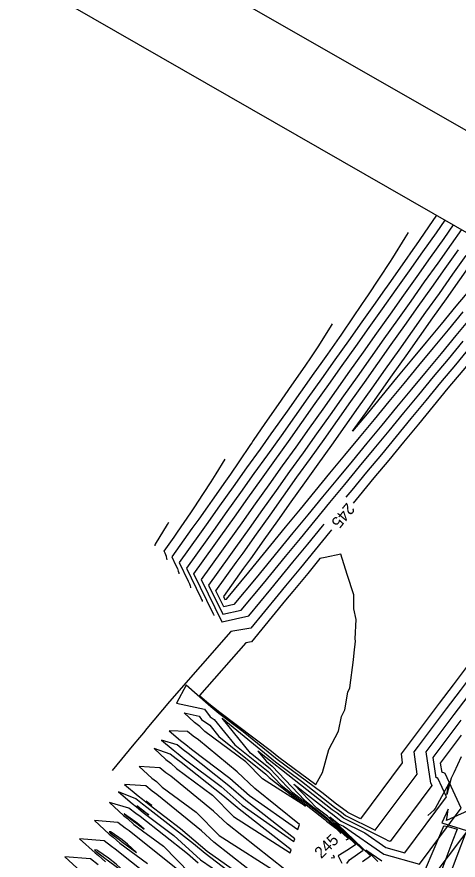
# Model space of a CAD drawing. Extents: x 1160447 to 1162032, y 616022 to 618272.
# Drawn here: x 1160902.9 to 1160997.8, y 616733 to 616914.4 of the extents above; entities that cross this region are included whole.
import ezdxf

# ---------------------------------------------------------------- set-up
doc = ezdxf.new("R2010")
doc.units = 0
for name, color, linetype in [('BORDER', 7, 'Continuous'), ('D_Contours_Major', 7, 'Continuous'), ('D_Contours_Minor', 7, 'Continuous'), ('Plot Boundary_1', 7, 'Continuous')]:
    doc.layers.add(name, color=color, linetype=linetype)

msp = doc.modelspace()

# ---------------------------------------------------------------- linework, layer by layer
at = {"layer": 'BORDER'}
msp.add_line((1161303.72, 616715.44), (1160848.31, 616976.65), dxfattribs=at)
at = {"layer": 'D_Contours_Major'}
for points in [[(1160945.35, 616785.57), (1160945.35, 616785.6), (1160945.33, 616785.67), (1160945.29, 616785.76), (1160945.23, 616785.9), (1160940.99, 616794.53), (1160945.35, 616800.64), (1160946.8, 616802.68), (1160949.71, 616806.75), (1160952.62, 616810.82), (1160955.52, 616814.9), (1160958.42, 616818.97), (1160961.32, 616823.05), (1160964.22, 616827.12), (1160967.12, 616831.2), (1160970.02, 616835.28), (1160972.92, 616839.36), (1160975.81, 616843.44), (1160978.71, 616847.52), (1160981.6, 616851.6), (1160984.49, 616855.69), (1160987.38, 616859.77), (1160990.27, 616863.85), (1160993.16, 616867.94), (1160995.07, 616870.64)], [(1161007.04, 616863.78), (1161006.95, 616863.68), (1161003.75, 616859.82), (1161000.56, 616855.97), (1160997.37, 616852.12), (1160994.18, 616848.27), (1160990.99, 616844.41), (1160987.8, 616840.56), (1160984.61, 616836.7), (1160981.42, 616832.84), (1160978.24, 616828.98), (1160975.15, 616825.24), (1160977.96, 616829.2), (1160980.85, 616833.28), (1160983.75, 616837.36), (1160986.65, 616841.44), (1160989.54, 616845.52), (1160992.43, 616849.6), (1160995.32, 616853.69), (1160998.21, 616857.77), (1161001.1, 616861.86), (1161003.78, 616865.65)], [(1160975.33, 616809.76), (1160976.62, 616811.32), (1160979.81, 616815.18), (1160982.99, 616819.04), (1160986.17, 616822.9), (1160989.36, 616826.76), (1160992.55, 616830.62), (1160995.73, 616834.47), (1160998.92, 616838.33), (1161001.83, 616841.84), (1161002.43, 616841.94), (1161006.15, 616842.54), (1161010.36, 616842.17), (1161015.21, 616841.72), (1161018.4, 616842.3), (1161024.16, 616843.33), (1161025.22, 616843.37), (1161027.33, 616843.88), (1161031.24, 616845.06), (1161035.35, 616846.28), (1161036.36, 616846.96)], [(1160932.68, 616800.56), (1160932.68, 616800.9), (1160932.68, 616800.9), (1160932.72, 616800.96), (1160935.32, 616805.18), (1160935.63, 616805.67)], [(1160970.58, 616803.99), (1160970.26, 616803.6), (1160967.08, 616799.74), (1160963.9, 616795.87), (1160960.73, 616792.01), (1160959.14, 616790.07), (1160953.22, 616782.87), (1160948.96, 616782.12), (1160935.72, 616767.07), (1160930.86, 616761.25), (1160930.13, 616760.38), (1160929.3, 616759.38), (1160928.07, 616757.9), (1160926.08, 616755.51), (1160925.42, 616754.72), (1160923.39, 616752.28)], [(1160999.76, 616774.69), (1160996.76, 616770.7), (1160993.75, 616766.7), (1160992.24, 616764.71), (1160987.73, 616758.72), (1160985.58, 616755.87), (1160985.82, 616753.88), (1160976.84, 616741.87), (1160974.12, 616743.21), (1160973.75, 616743.5), (1160971.71, 616745), (1160968.51, 616747.53), (1160958.93, 616754.62), (1160951.61, 616760.58), (1160946.36, 616764.52), (1160944.67, 616765.98), (1160944.06, 616766.45), (1160939.32, 616770.58), (1160937.26, 616766.74), (1160943.28, 616765.43), (1160944.53, 616763.8), (1160945.35, 616763.21), (1160949.8, 616757.77), (1160956.95, 616752.04), (1160959.76, 616749.08), (1160969.2, 616741.72), (1160969.56, 616741.37), (1160971.54, 616739.84), (1160972.64, 616738.78), (1160972.43, 616738.69)], [(1160998.49, 616755.2), (1160996.89, 616751.74), (1160996.37, 616750.6), (1160995.42, 616747.11), (1160995.84, 616749.45), (1160994.27, 616746.55), (1160992.93, 616744.07), (1160992.58, 616743.74), (1160991.35, 616742.56)], [(1161001.54, 616744.28), (1160995.35, 616741.48), (1160995.48, 616742.28), (1160995.71, 616743.93), (1160994.34, 616741.02), (1160994.97, 616740.81), (1160995.08, 616740.79), (1160999.65, 616739.35)], [(1160992.71, 616729.7), (1161001.7, 616741.71), (1161000.68, 616743.9)], [(1160999.34, 616738.53), (1160997.56, 616733.84), (1160995.76, 616729.09)], [(1160980.58, 616732.7), (1160977.99, 616735.17), (1160981.43, 616732.8)]]:
    msp.add_lwpolyline(points, dxfattribs=at)
at = {"layer": 'D_Contours_Minor'}
for points in [[(1160993.16, 616871.74), (1160991.46, 616869.24), (1160988.64, 616865.11), (1160988.6, 616865.05), (1160985.77, 616861.01), (1160982.9, 616856.91), (1160981.67, 616855.16), (1160980.01, 616852.82), (1160977.12, 616848.74), (1160974.23, 616844.66), (1160971.33, 616840.58), (1160968.43, 616836.5), (1160965.54, 616832.42), (1160962.64, 616828.34), (1160959.74, 616824.26), (1160956.83, 616820.19), (1160953.93, 616816.11), (1160951.03, 616812.04), (1160948.12, 616807.97), (1160945.22, 616803.89), (1160943.76, 616801.86), (1160939.4, 616795.75), (1160942.51, 616789.42), (1160942.67, 616789.07), (1160942.77, 616788.82), (1160942.81, 616788.66), (1160942.81, 616788.57)], [(1160996.81, 616869.64), (1160994.75, 616866.72), (1160991.86, 616862.64), (1160988.97, 616858.55), (1160986.08, 616854.47), (1160983.19, 616850.39), (1160980.3, 616846.3), (1160977.4, 616842.22), (1160974.5, 616838.14), (1160971.61, 616834.06), (1160968.71, 616829.99), (1160965.81, 616825.91), (1160962.91, 616821.83), (1160960.01, 616817.76), (1160957.11, 616813.68), (1160954.2, 616809.61), (1160951.3, 616805.53), (1160948.39, 616801.46), (1160946.94, 616799.42), (1160942.58, 616793.32), (1160947.03, 616784.25), (1160947.07, 616784.24), (1160952.79, 616785.49), (1160957.55, 616791.29), (1160959.14, 616793.22), (1160962.32, 616797.09), (1160965.5, 616800.95), (1160968.67, 616804.82), (1160969.04, 616805.26)], [(1160987.12, 616867.96), (1160986.4, 616866.82), (1160983.73, 616862.57), (1160983.1, 616861.56), (1160980.99, 616858.37), (1160978.23, 616854.18), (1160978.14, 616854.04), (1160975.41, 616850.05), (1160972.58, 616845.92), (1160972.25, 616845.43), (1160969.71, 616841.82), (1160968.28, 616839.78), (1160966.83, 616837.73), (1160963.94, 616833.64), (1160961.04, 616829.56), (1160958.15, 616825.48), (1160957.57, 616824.67), (1160955.25, 616821.4), (1160952.34, 616817.33), (1160949.44, 616813.26), (1160946.54, 616809.18), (1160943.63, 616805.11), (1160942.18, 616803.07), (1160937.82, 616796.97), (1160939.79, 616792.95), (1160940.06, 616792.37), (1160940.21, 616791.98), (1160940.28, 616791.72), (1160940.28, 616791.56)], [(1160998.56, 616868.64), (1160996.34, 616865.51), (1160993.45, 616861.42), (1160990.56, 616857.34), (1160987.67, 616853.25), (1160984.78, 616849.17), (1160981.88, 616845.09), (1160978.99, 616841.01), (1160976.09, 616836.93), (1160973.2, 616832.85), (1160970.3, 616828.77), (1160967.4, 616824.69), (1160964.5, 616820.61), (1160961.6, 616816.54), (1160958.69, 616812.46), (1160955.79, 616808.39), (1160952.89, 616804.32), (1160949.98, 616800.24), (1160948.53, 616798.21), (1160944.17, 616792.1), (1160947.23, 616785.85), (1160947.26, 616785.85), (1160951.2, 616786.71), (1160955.97, 616792.51), (1160957.55, 616794.44), (1160960.73, 616798.31), (1160963.91, 616802.17), (1160967.09, 616806.03), (1160970.27, 616809.89), (1160973.45, 616813.76), (1160976.63, 616817.62), (1160979.81, 616821.48), (1160983, 616825.34), (1160986.18, 616829.19), (1160989.37, 616833.05), (1160992.56, 616836.91), (1160995.75, 616840.76), (1160998.94, 616844.62)], [(1161000.54, 616849.69), (1160997.35, 616845.83), (1160994.16, 616841.98), (1160990.97, 616838.12), (1160987.78, 616834.27), (1160984.6, 616830.41), (1160981.41, 616826.55), (1160978.23, 616822.69), (1160975.04, 616818.83), (1160971.86, 616814.97), (1160968.68, 616811.11), (1160965.5, 616807.25), (1160962.32, 616803.39), (1160959.14, 616799.52), (1160955.97, 616795.66), (1160954.38, 616793.72), (1160949.61, 616787.93), (1160947.45, 616787.45), (1160947.44, 616787.46), (1160945.75, 616790.88), (1160950.11, 616796.99), (1160951.57, 616799.03), (1160954.47, 616803.1), (1160957.38, 616807.17), (1160960.28, 616811.25), (1160963.18, 616815.32), (1160966.09, 616819.4), (1160968.99, 616823.47), (1160971.88, 616827.55), (1160974.78, 616831.63), (1160977.68, 616835.71), (1160980.58, 616839.79), (1160983.47, 616843.87), (1160986.36, 616847.95), (1160989.26, 616852.04), (1160992.15, 616856.12), (1160995.04, 616860.21), (1160997.93, 616864.29)], [(1160999.51, 616863.07), (1160996.62, 616858.99), (1160993.73, 616854.9), (1160990.84, 616850.82), (1160987.95, 616846.74), (1160985.06, 616842.66), (1160982.16, 616838.57), (1160979.27, 616834.49), (1160976.37, 616830.41), (1160973.47, 616826.34), (1160970.57, 616822.26), (1160967.67, 616818.18), (1160964.77, 616814.11), (1160961.87, 616810.03), (1160958.97, 616805.96), (1160956.06, 616801.88), (1160953.15, 616797.81), (1160951.7, 616795.78), (1160947.34, 616789.67), (1160947.64, 616789.06), (1160947.64, 616789.06), (1160948.03, 616789.14), (1160952.79, 616794.94), (1160954.38, 616796.87), (1160957.56, 616800.74), (1160960.73, 616804.6), (1160963.91, 616808.47), (1160967.09, 616812.33), (1160970.27, 616816.19), (1160973.46, 616820.05), (1160976.64, 616823.91), (1160979.82, 616827.77), (1160983.01, 616831.63), (1160986.2, 616835.48), (1160989.38, 616839.34), (1160992.57, 616843.2), (1160995.76, 616847.05), (1160998.96, 616850.9)], [(1160973.79, 616811.03), (1160975.04, 616812.54), (1160978.22, 616816.4), (1160981.4, 616820.26), (1160984.59, 616824.12), (1160987.77, 616827.98), (1160990.96, 616831.83), (1160994.15, 616835.69), (1160997.34, 616839.55), (1161000.53, 616843.4), (1161003.72, 616847.25), (1161006.91, 616851.11), (1161010.1, 616854.96), (1161013.3, 616858.81), (1161014.07, 616859.74)], [(1160970.75, 616848.31), (1160970.33, 616847.64), (1160967.66, 616843.39), (1160966.24, 616841.23), (1160964.88, 616839.22), (1160962.01, 616835.12), (1160959.15, 616831.01), (1160956.28, 616826.91), (1160953.78, 616823.21), (1160953.48, 616822.76), (1160953.21, 616822.36), (1160950.66, 616818.62), (1160948.87, 616815.99), (1160947.82, 616814.5), (1160944.94, 616810.41), (1160943.91, 616808.94), (1160942.04, 616806.33), (1160940.59, 616804.29), (1160936.23, 616798.18), (1160937.07, 616796.47), (1160937.44, 616795.68), (1160937.65, 616795.14), (1160937.75, 616794.78), (1160937.75, 616794.56)], [(1160935.22, 616797.56), (1160935.21, 616797.84), (1160935.09, 616798.29), (1160934.82, 616798.98), (1160934.62, 616799.42), (1160936.77, 616802.48), (1160937.48, 616803.52), (1160938.9, 616805.59), (1160940.31, 616807.65), (1160941.04, 616808.73), (1160943.08, 616811.83), (1160944.72, 616814.33), (1160945.79, 616816.06), (1160947.76, 616819.24)], [(1160973.75, 616737.36), (1160974.23, 616737.57), (1160971.67, 616740.01), (1160970.16, 616741.18), (1160969.37, 616741.94), (1160962.32, 616747.44), (1160957.4, 616752.62), (1160953.21, 616755.98), (1160947.06, 616763.5), (1160958.56, 616754.13), (1160964.18, 616749.97), (1160971.25, 616744.39), (1160972.77, 616743.28), (1160973.64, 616742.59), (1160980.01, 616739.43), (1160989, 616751.45), (1160988.4, 616756.28), (1160989.32, 616757.5), (1160993.83, 616763.49), (1160995.34, 616765.49), (1160998.34, 616769.48), (1161001.35, 616773.48), (1161003.2, 616775.94)], [(1160999.93, 616768.26), (1160996.92, 616764.27), (1160995.42, 616762.27), (1160990.91, 616756.28), (1160991.9, 616749.52), (1160991.91, 616749.52), (1160991.92, 616749.52), (1160991.93, 616749.51), (1160991.94, 616749.51), (1160992.17, 616749.01), (1160983.19, 616737), (1160982.77, 616737.11), (1160982.29, 616737.44), (1160973.17, 616741.96), (1160971.79, 616743.05), (1160970.78, 616743.78), (1160959.85, 616752.42), (1160958.19, 616753.65), (1160954.79, 616756.42), (1160956.61, 616754.2), (1160957.84, 616753.21), (1160964.88, 616745.8), (1160969.54, 616742.17), (1160970.76, 616740.99), (1160971.8, 616740.18), (1160975.81, 616736.35), (1160974.27, 616735.24), (1160972.07, 616733.88), (1160972.86, 616732.32)], [(1160973.88, 616732.23), (1160974.49, 616733.04), (1160977.4, 616735.13), (1160971.93, 616740.35), (1160971.36, 616740.8), (1160969.71, 616742.39), (1160967.44, 616744.16), (1160962.53, 616749.33), (1160970.32, 616743.18), (1160970.81, 616742.82), (1160972.69, 616741.34), (1160977.74, 616738.84), (1160982.32, 616735.67), (1160986.36, 616734.57), (1160995.35, 616746.58), (1160993.49, 616750.57), (1160993.42, 616750.61), (1160993.33, 616750.64), (1160993.24, 616750.66), (1160993.14, 616750.67), (1160992.49, 616755.07), (1160997.01, 616761.06), (1160998.51, 616763.05)], [(1160977.28, 616732.69), (1160978.99, 616733.92), (1160972.07, 616740.53), (1160971.95, 616740.61), (1160970.26, 616742.25), (1160972.21, 616740.72), (1160973.18, 616740.24), (1160981.88, 616734.24), (1160989.54, 616732.13), (1160998.52, 616744.15), (1160995.03, 616751.63), (1160994.9, 616751.71), (1160994.74, 616751.77), (1160994.57, 616751.81), (1160994.38, 616751.82), (1160994.08, 616753.85), (1160998.59, 616759.84)], [(1160960.56, 616730.94), (1160948.24, 616740.67), (1160945.23, 616743.5), (1160936.03, 616751.04), (1160934.98, 616751.75), (1160933.64, 616752.85), (1160929.26, 616753.08), (1160931.93, 616750.62), (1160932.93, 616749.85), (1160934.21, 616748.66), (1160941.49, 616743.28), (1160946.41, 616738.27), (1160959.69, 616729.79)], [(1160956.29, 616728.2), (1160945.3, 616736.82), (1160942.67, 616739.29), (1160933.04, 616747.12), (1160932.05, 616747.79), (1160930.65, 616748.93), (1160926.04, 616749.21), (1160929, 616746.78), (1160929.95, 616746.05), (1160931.35, 616744.9), (1160938.15, 616739.79), (1160943.85, 616734.91), (1160954.58, 616727.28)], [(1160953.43, 616726.72), (1160943.45, 616734.39), (1160940.91, 616736.49), (1160930.9, 616744.31), (1160929.96, 616744.99), (1160928.51, 616746.12), (1160924.76, 616747.66), (1160927.74, 616745.12), (1160928.67, 616744.41), (1160930.06, 616743.22), (1160936.7, 616738.26), (1160942.44, 616733.06), (1160952.46, 616726.18)], [(1160941.89, 616732.34), (1160939.6, 616734.31), (1160929.41, 616742.35), (1160928.5, 616743), (1160927.02, 616744.17), (1160922.83, 616745.34), (1160925.83, 616742.6), (1160926.72, 616741.91), (1160928.1, 616740.64), (1160934.49, 616735.94), (1160940.21, 616730.12)], [(1160937.52, 616730.86), (1160927.06, 616739.27), (1160926.19, 616739.86), (1160924.67, 616741.08), (1160919.62, 616741.46), (1160922.78, 616738.58), (1160923.63, 616737.93), (1160925.06, 616736.62), (1160931.03, 616732.24)], [(1160981.52, 616712.33), (1160981.94, 616712.77), (1160982.95, 616713.97), (1160983.78, 616715.55), (1160985.5, 616718.89), (1160986.77, 616721.75), (1160989.52, 616727.87), (1160990.84, 616731.02), (1160994.09, 616738.75), (1160994.76, 616740.34), (1160994.79, 616740.34), (1160994.81, 616740.34), (1160995.68, 616740.22), (1160997.61, 616739.61), (1160997.48, 616739.27), (1160996.73, 616737.29), (1160993.9, 616729.82), (1160991.21, 616722.63), (1160990.36, 616720.36), (1160989.48, 616718), (1160986.85, 616710.89), (1160985.95, 616708.44)], [(1160934.95, 616726.65), (1160924.08, 616735.33), (1160923.26, 616735.89), (1160921.69, 616737.14), (1160916.42, 616737.58), (1160919.74, 616734.57), (1160920.51, 616733.98), (1160922.01, 616732.6)], [(1160920.41, 616731.95), (1160918.76, 616733.26), (1160913.22, 616733.69), (1160916.7, 616730.55)], [(1160970.51, 616733.48), (1160971.27, 616733.53), (1160971.03, 616734)]]:
    msp.add_lwpolyline(points, dxfattribs=at)
for points in [[(1160945.85, 616765.39), (1160946.56, 616764.78), (1160957.71, 616756.39), (1160959.29, 616755.1), (1160967.2, 616749.25), (1160968.65, 616751.84), (1160970, 616756.75), (1160972.11, 616760.74), (1160972.77, 616763.88), (1160973.5, 616765.32), (1160974.15, 616769.12), (1160974.58, 616770), (1160975.34, 616776.03), (1160975.49, 616777.55), (1160975.74, 616780.08), (1160975.66, 616780.56), (1160975.94, 616784.75), (1160975.4, 616787.06), (1160975.39, 616790.03), (1160973.99, 616794.44), (1160972.6, 616798.76), (1160969.25, 616798.08), (1160968.11, 616797.84), (1160965.49, 616794.66), (1160962.32, 616790.79), (1160960.73, 616788.86), (1160953.38, 616779.91), (1160952.14, 616779.69), (1160942.21, 616768.4), (1160944.21, 616766.65)], [(1160942.13, 616763.94), (1160942.67, 616763.24), (1160944.41, 616761.99), (1160946.4, 616759.55), (1160956.5, 616751.45), (1160957.2, 616750.72), (1160965.03, 616744.61), (1160955.76, 616750.48), (1160952.2, 616754.12), (1160943.39, 616760.64), (1160942.26, 616761.7), (1160941.1, 616762.6), (1160938.9, 616764.64)], [(1160940.83, 616759.63), (1160939.61, 616760.64), (1160935.69, 616760.8), (1160938.14, 616758.73), (1160939.24, 616757.87), (1160940.47, 616756.83), (1160948.71, 616750.63), (1160952.97, 616746.84), (1160963.38, 616739.58), (1160963.73, 616740.65), (1160954.12, 616748.35), (1160950.33, 616751.94), (1160942, 616758.83)], [(1160938.67, 616756.73), (1160937.39, 616757.75), (1160934.03, 616758.81), (1160936.57, 616756.68), (1160937.65, 616755.85), (1160938.9, 616754.79), (1160946.88, 616748.78), (1160951.4, 616744.8), (1160962.53, 616736.98), (1160962.72, 616737.58), (1160952.19, 616745.83), (1160948.5, 616748.98), (1160939.78, 616755.93)], [(1160937.2, 616754.75), (1160935.89, 616755.79), (1160932.48, 616756.95), (1160934.99, 616754.62), (1160936.04, 616753.81), (1160937.27, 616752.66), (1160945.04, 616746.92), (1160949.52, 616742.34), (1160961.74, 616734.55), (1160961.93, 616735.16), (1160950.72, 616743.91), (1160947.23, 616746.87), (1160938.27, 616753.97)], [(1160930.25, 616743.46), (1160930.2, 616743.51), (1160928.7, 616744.66), (1160930.28, 616743.51), (1160930.66, 616743.21), (1160931.3, 616742.68)], [(1160931.47, 616745.07), (1160931.45, 616745.09), (1160930.76, 616745.62), (1160931.5, 616745.11), (1160931.68, 616744.97), (1160931.96, 616744.71)], [(1160926.07, 616742.89), (1160926.06, 616742.91), (1160926.01, 616742.92), (1160926.05, 616742.89), (1160928.32, 616741.13), (1160928.42, 616741.05), (1160930.31, 616739.65), (1160929.17, 616740.63), (1160928.5, 616741.16)], [(1160923.2, 616738.95), (1160923.11, 616739.02), (1160922.81, 616739.04), (1160923, 616738.87), (1160925.21, 616737.17), (1160925.37, 616737.03), (1160928.68, 616734.6), (1160926.73, 616736.4), (1160925.59, 616737.32)], [(1160920.32, 616734.99), (1160920.16, 616735.12), (1160919.61, 616735.17), (1160919.96, 616734.85), (1160922.1, 616733.21), (1160922.32, 616733.01), (1160927.05, 616729.54), (1160924.25, 616732.12), (1160922.63, 616733.41)]]:
    msp.add_lwpolyline(points, close=True, dxfattribs=at)
at = {"layer": 'Plot Boundary_1'}
msp.add_lwpolyline([(1160500.57, 616331.28), (1160855.78, 616950.54), (1161275.71, 616709.67), (1160920.5, 616090.41)], close=True, dxfattribs=at)

# ---------------------------------------------------------------- texts
at = {"layer": 'D_Contours_Major'}
for rotation, p in [(230.5271, (1160973.92, 616810)), (44.7625, (1160968.41, 616733.15))]:
    msp.add_text('245', height=2.49, rotation=rotation, dxfattribs=at).set_placement(p)

doc.saveas('drawing.dxf')
